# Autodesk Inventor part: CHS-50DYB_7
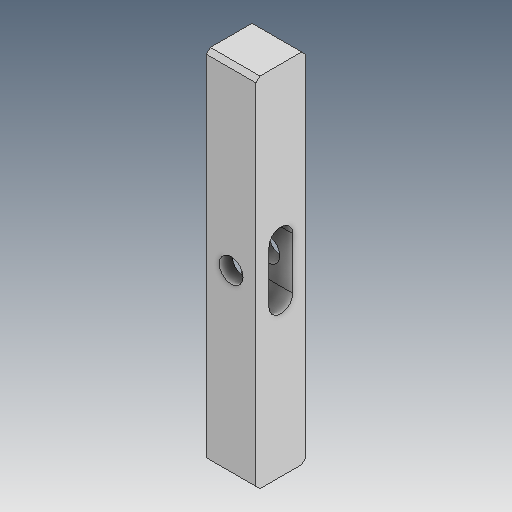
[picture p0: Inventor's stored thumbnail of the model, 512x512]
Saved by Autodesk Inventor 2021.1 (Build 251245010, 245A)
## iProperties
Created: 2019-04
Part Number: CHS-50DYB_7
Material: Ogólny
Document SubType Name: Modeling
Designer: user
Density: 1 g/cm^3
Appearance: Domyślna
Author: user
Revision Number: ÈÎºÎ
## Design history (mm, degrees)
feature "ÊäÈë1"
node "Bryła1"
